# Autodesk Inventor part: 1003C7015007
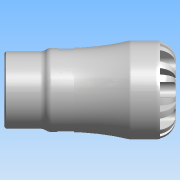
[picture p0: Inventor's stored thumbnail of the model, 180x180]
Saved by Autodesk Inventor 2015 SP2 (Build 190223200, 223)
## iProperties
Created: 2016-12
Part Number: 1003C7015007
Material: PVC-Piping
Description: PLASSON FEMALE COPPER ADAPTOR 15X3/4" SERIES 1
Document SubType Name: Modeling
Designer: KIM
Mass: 664.223 g
Surface Area: 733.008 cm^2
Volume: 474.445 cm^3
Density: 1.4 g/cm^3
Appearance: Smooth - White
Author: KIM
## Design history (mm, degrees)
derived "1003C.ipt"
feature "Solid1::1003C.ipt"
tag "TaggingFeature1"
body "Solid1"
other parameters: "d0" = 71, "d1" = 18.9, "d2" = 15, "d3" = 24.6, "d4" = 41, "d6" = 45, "d8" = 34.85, "d13" = 6.56, "d14" = 6.56, "d15" = 0, "d17" = 360 deg, "d19" = 8 deg, "d20" = 0.3, "d21" = 0.3, "d22" = 8 deg, "d24" = 0, "d26" = 360 deg, "d32" = 4.1, "d33" = 4.1, "d39" = 0.72351, "d42" = 24.117, "d43" = 31.98, "d46" = 1.25, "d47" = 18, "d48" = 22.91115, "d50" = 2.64, "d51" = 0.41, "d54" = 6.97, "d55" = 4.51, "d57" = 17.444, "d58" = 0, "d68" = 360 deg, "d72" = 0.3, "d74" = 0, "d76" = 5.9245, "d_" = 15, "E_" = 41, "H_" = 71, "l_" = 45, "Rp" = 24.117, "l_2" = 18, "d9" = 8.2, "d11" = 41, "d12" = 24.6, "d49" = 8
